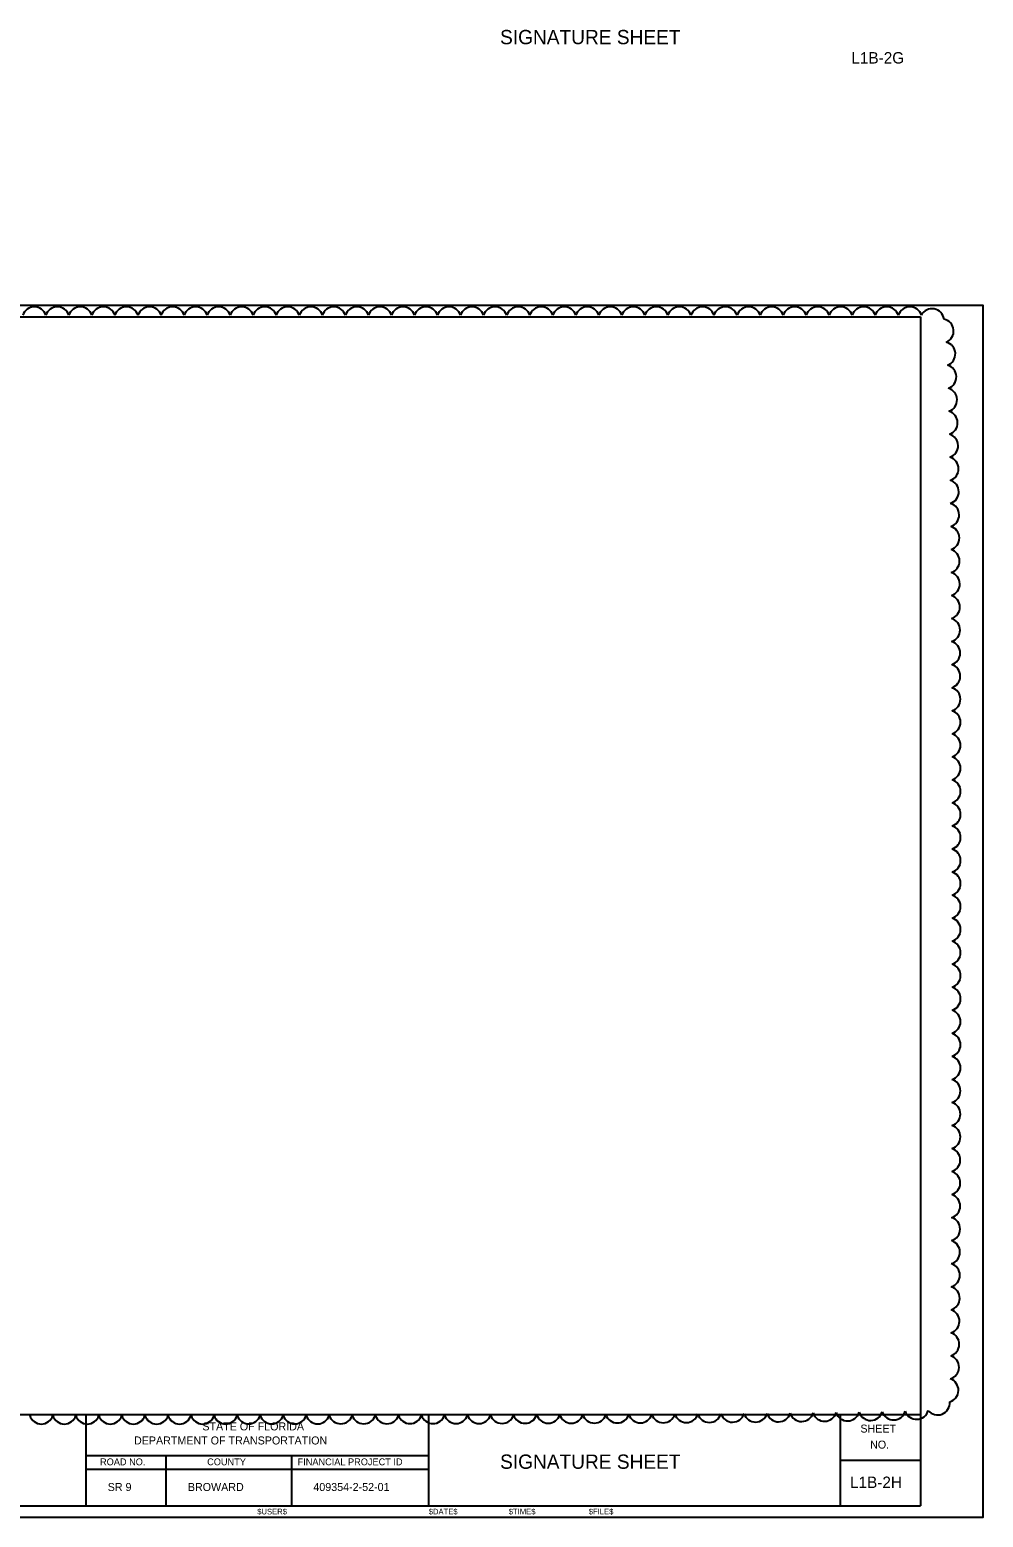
# Model space of a CAD drawing. Extents: x -811.2 to -755.6, y -2295.2 to -2235.1.
# Drawn here: x -775.75 to -767.41, y -2282.95 to -2269.93 of the extents above; entities that cross this region are included whole.
import ezdxf

# ---------------------------------------------------------------- set-up
doc = ezdxf.new("R2010")
doc.units = 0
for name, color, linetype in [('Cloud_dp', 7, 'Continuous'), ('PlotBorder_dp', 7, 'Continuous'), ('SheetBorder_dp', 7, 'Continuous'), ('SheetLines_dp', 7, 'Continuous'), ('TextMinor', 7, 'Continuous'), ('TextMisc', 7, 'Continuous'), ('TextShtNo', 7, 'Continuous')]:
    doc.layers.add(name, color=color, linetype=linetype)

msp = doc.modelspace()

# ---------------------------------------------------------------- linework, layer by layer
at = {"layer": 'Cloud_dp'}
for centre, start, end in [((-775.707, -2272.463), 17.5, 162.5), ((-775.505, -2272.463), 17.5, 162.5), ((-775.304, -2272.463), 17.5, 162.5), ((-775.102, -2272.463), 17.5, 162.5), ((-774.901, -2272.463), 17.5, 162.5), ((-774.699, -2272.463), 17.5, 162.5), ((-774.498, -2272.463), 17.5, 162.5), ((-774.296, -2272.463), 17.5, 162.5), ((-774.095, -2272.463), 17.5, 162.5), ((-773.893, -2272.463), 17.5, 162.5), ((-773.691, -2272.463), 17.5, 162.5), ((-773.49, -2272.463), 17.5, 162.5), ((-773.288, -2272.463), 17.5, 162.5), ((-773.087, -2272.463), 17.5, 162.5), ((-772.885, -2272.463), 17.5, 162.5), ((-772.684, -2272.463), 17.5, 162.5), ((-772.482, -2272.463), 17.5, 162.5), ((-772.281, -2272.463), 17.5, 162.5), ((-772.079, -2272.463), 17.5, 162.5), ((-771.878, -2272.463), 17.5, 162.5), ((-771.676, -2272.463), 17.5, 162.5), ((-771.474, -2272.463), 17.5, 162.5), ((-771.273, -2272.463), 17.5, 162.5), ((-771.071, -2272.463), 17.5, 162.5), ((-770.87, -2272.463), 17.5, 162.5), ((-770.668, -2272.463), 17.5, 162.5), ((-770.467, -2272.463), 17.5, 162.5), ((-770.265, -2272.463), 17.5, 162.5), ((-770.064, -2272.463), 17.5, 162.5), ((-769.862, -2272.463), 17.5, 162.5), ((-769.661, -2272.463), 17.5, 162.5), ((-769.459, -2272.463), 17.5, 162.5), ((-769.257, -2272.463), 17.5, 162.5), ((-769.056, -2272.463), 17.5, 162.5), ((-768.854, -2272.463), 17.5, 162.5), ((-768.653, -2272.463), 17.5, 162.5), ((-768.451, -2272.463), 17.5, 162.5), ((-768.25, -2272.463), 17.5, 162.5), ((-768.048, -2272.463), 17.5, 162.5), ((-767.854, -2272.48), 7.7061, 152.7061), ((-767.771, -2272.569), 293.1451, 78.1451), ((-767.756, -2272.769), 290.3535, 75.3535), ((-767.747, -2272.97), 289.5186, 74.5186), ((-767.741, -2273.171), 289.0656, 74.0656), ((-767.736, -2273.372), 288.7699, 73.7699), ((-767.732, -2273.573), 288.5573, 73.5573), ((-767.728, -2273.775), 288.3949, 73.3949), ((-767.726, -2273.976), 288.2656, 73.2656), ((-767.723, -2274.178), 288.1595, 73.1595), ((-767.721, -2274.379), 288.0704, 73.0704), ((-767.719, -2274.581), 287.9942, 72.9942), ((-767.717, -2274.782), 287.928, 72.928), ((-767.716, -2274.984), 287.8698, 72.8698), ((-767.715, -2275.185), 287.8182, 72.8182), ((-767.714, -2275.387), 287.772, 72.772), ((-767.713, -2275.588), 287.7302, 72.7302), ((-767.712, -2275.79), 287.6923, 72.6923), ((-767.711, -2275.991), 287.6577, 72.6577), ((-767.711, -2276.193), 287.6259, 72.6259), ((-767.711, -2276.394), 287.5965, 72.5965), ((-767.71, -2276.596), 287.5693, 72.5693), ((-767.71, -2276.798), 287.544, 72.544), ((-767.71, -2276.999), 287.5204, 72.5204), ((-767.71, -2277.201), 287.5008, 72.5008), ((-767.71, -2277.402), 287.4924, 72.4924), ((-767.71, -2277.604), 287.4849, 72.4849), ((-767.71, -2277.805), 287.4769, 72.4769), ((-767.71, -2278.007), 287.4682, 72.4682), ((-767.71, -2278.208), 287.4589, 72.4589), ((-767.71, -2278.41), 287.4488, 72.4488), ((-767.711, -2278.611), 287.4378, 72.4378), ((-767.711, -2278.813), 287.4258, 72.4258), ((-767.711, -2279.015), 287.4126, 72.4126), ((-767.712, -2279.216), 287.398, 72.398), ((-767.712, -2279.418), 287.3817, 72.3817), ((-767.712, -2279.619), 287.3633, 72.3633), ((-767.713, -2279.821), 287.3425, 72.3425), ((-767.713, -2280.022), 287.3185, 72.3185), ((-767.714, -2280.224), 287.2905, 72.2905), ((-767.715, -2280.425), 287.2573, 72.2573), ((-767.716, -2280.627), 287.217, 72.217), ((-767.717, -2280.828), 287.1666, 72.1666), ((-767.718, -2281.03), 287.101, 72.101), ((-767.72, -2281.231), 287.0106, 72.0106), ((-767.722, -2281.433), 286.8744, 71.8744), ((-767.724, -2281.634), 286.6317, 71.6317), ((-767.729, -2281.835), 285.9387, 70.9387), ((-767.805, -2281.945), 219.2472, 4.2472), ((-775.646, -2282.024), 197.4989, 342.4989), ((-775.445, -2282.024), 197.5044, 342.5044), ((-775.243, -2282.024), 197.5105, 342.5105), ((-775.042, -2282.024), 197.5167, 342.5167), ((-774.84, -2282.024), 197.5233, 342.5233), ((-774.638, -2282.024), 197.5301, 342.5301), ((-774.437, -2282.024), 197.5372, 342.5372), ((-774.235, -2282.024), 197.5447, 342.5447), ((-774.034, -2282.024), 197.5525, 342.5525), ((-773.832, -2282.023), 197.5607, 342.5607), ((-773.631, -2282.023), 197.5693, 342.5693), ((-773.429, -2282.023), 197.5784, 342.5784), ((-773.228, -2282.023), 197.5879, 342.5879), ((-773.026, -2282.022), 197.598, 342.598), ((-772.825, -2282.022), 197.6087, 342.6087), ((-772.623, -2282.022), 197.62, 342.62), ((-772.421, -2282.021), 197.6321, 342.6321), ((-772.22, -2282.021), 197.6449, 342.6449), ((-772.018, -2282.02), 197.6587, 342.6587), ((-771.817, -2282.02), 197.6734, 342.6734), ((-771.615, -2282.019), 197.6893, 342.6893), ((-771.414, -2282.018), 197.7064, 342.7064), ((-771.212, -2282.017), 197.725, 342.725), ((-771.011, -2282.017), 197.7453, 342.7453), ((-770.809, -2282.016), 197.7675, 342.7675), ((-770.608, -2282.015), 197.792, 342.792), ((-770.406, -2282.014), 197.8192, 342.8192), ((-770.205, -2282.013), 197.8496, 342.8496), ((-770.003, -2282.011), 197.8839, 342.8839), ((-769.802, -2282.01), 197.9231, 342.9231), ((-769.6, -2282.008), 197.9684, 342.9684), ((-769.398, -2282.007), 198.0216, 343.0216), ((-769.197, -2282.005), 198.0853, 343.0853), ((-768.995, -2282.002), 198.1633, 343.1633), ((-768.794, -2282), 198.2623, 343.2623), ((-768.593, -2281.997), 198.3936, 343.3936), ((-768.391, -2281.993), 198.5799, 343.5799), ((-768.19, -2281.989), 198.8753, 343.8753), ((-767.989, -2281.983), 199.4643, 344.4643)]:
    msp.add_arc(centre, 0.106, start, end, dxfattribs=at)
at = {"layer": 'PlotBorder_dp'}
msp.add_lwpolyline([(-783.906, -2282.946), (-767.406, -2282.946), (-767.406, -2272.346), (-783.906, -2272.346)], close=True, dxfattribs=at)
at = {"layer": 'SheetBorder_dp'}
for p, q in [((-783.356, -2272.446), (-767.956, -2272.446)), ((-767.956, -2272.446), (-767.956, -2282.846)), ((-783.356, -2282.046), (-767.956, -2282.046)), ((-783.356, -2282.846), (-767.956, -2282.846))]:
    msp.add_line(p, q, dxfattribs=at)
at = {"layer": 'SheetLines_dp'}
for p, q in [((-775.256, -2282.046), (-775.256, -2282.846)), ((-772.256, -2282.846), (-772.256, -2282.046)), ((-768.656, -2282.846), (-768.656, -2282.046)), ((-775.256, -2282.406), (-772.256, -2282.406)), ((-774.556, -2282.406), (-774.556, -2282.846)), ((-773.456, -2282.406), (-773.456, -2282.846)), ((-768.656, -2282.446), (-767.956, -2282.446)), ((-775.256, -2282.526), (-772.256, -2282.526))]:
    msp.add_line(p, q, dxfattribs=at)

# ---------------------------------------------------------------- texts
at = {"layer": 'TextMinor'}
msp.add_text('$USER$', height=0.05, dxfattribs=at).set_placement((-773.757, -2282.921))
for s, p in [('$DATE$', (-772.257, -2282.921)), ('$TIME$', (-771.557, -2282.921)), ('$FILE$', (-770.857, -2282.921))]:
    msp.add_text(s, height=0.05, rotation=360, dxfattribs=at).set_placement(p)
at = {"layer": 'TextMisc'}
for s, height, p in [('       SIGNATURE SHEET         ', 0.125, (-771.958, -2270.06)), ('STATE OF FLORIDA', 0.07, (-774.237, -2282.186)), ('DEPARTMENT OF TRANSPORTATION', 0.07, (-774.835, -2282.309)), ('ROAD NO.', 0.06, (-775.132, -2282.491)), ('COUNTY', 0.06, (-774.195, -2282.491)), ('FINANCIAL PROJECT ID', 0.06, (-773.404, -2282.491)), ('       SIGNATURE SHEET         ', 0.125, (-771.958, -2282.522)), (' SR 9  ', 0.07, (-775.091, -2282.716)), ('  BROWARD   ', 0.07, (-774.416, -2282.716)), ('409354-2-52-01', 0.07, (-773.266, -2282.716))]:
    msp.add_text(s, height=height, dxfattribs=at).set_placement(p)
for s, p in [('SHEET', (-768.481, -2282.205)), ('NO.', (-768.396, -2282.345))]:
    msp.add_text(s, height=0.07, rotation=359.8607, dxfattribs=at).set_placement(p)
at = {"layer": 'TextShtNo'}
for s, p in [('L1B-2G ', (-768.559, -2270.229)), ('L1B-2H ', (-768.571, -2282.69))]:
    msp.add_text(s, height=0.1, dxfattribs=at).set_placement(p)

doc.saveas('drawing.dxf')
